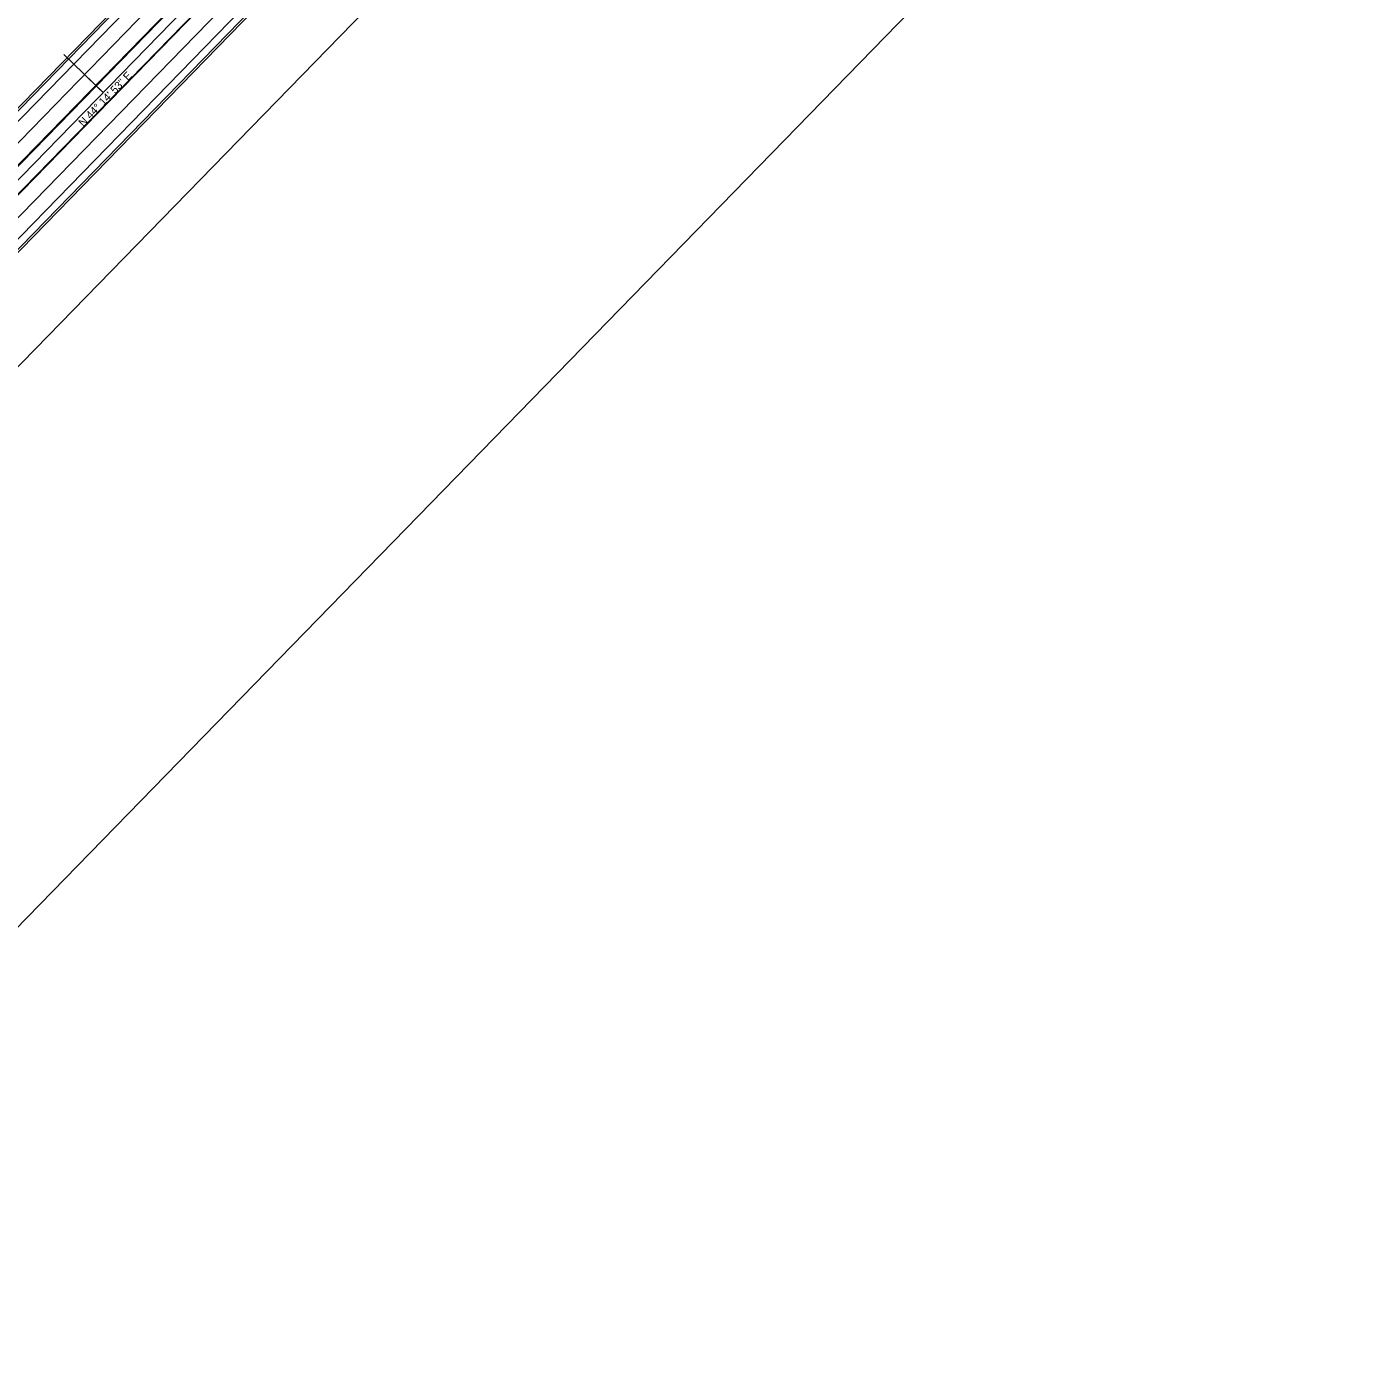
# Model space of a CAD drawing. Extents: x 2358865 to 2362945, y 393485 to 404880.
# Drawn here: x 2360577 to 2361590, y 398037 to 399070 of the extents above; entities that cross this region are included whole.
import ezdxf

# ---------------------------------------------------------------- set-up
doc = ezdxf.new("R2010")
doc.units = 0
for name, color, linetype in [('CL', 7, 'Continuous'), ('Level 19', 7, 'Continuous'), ('Level 21', 7, 'Continuous'), ('Level 25', 7, 'Continuous'), ('Level 27', 7, 'Continuous'), ('Level 30', 7, 'Continuous'), ('Level 35', 7, 'Continuous'), ('Level 37', 7, 'Continuous'), ('Level 39', 7, 'Continuous'), ('Level 41', 7, 'Continuous'), ('Level 48', 7, 'Continuous'), ('Level 58', 7, 'Continuous'), ('Level 63', 7, 'Continuous'), ('STAEQU', 7, 'Continuous')]:
    doc.layers.add(name, color=color, linetype=linetype)

msp = doc.modelspace()

# ---------------------------------------------------------------- linework, layer by layer
at = {"layer": 'CL'}
msp.add_line((2359688.9, 398047.8), (2361589.9, 399999.4), dxfattribs=at)
at = {"layer": 'Level 19'}
for p, q in [((2359821.6, 398212.7), (2361205.3, 399633.2)), ((2359850.3, 398184.8), (2361234, 399605.3))]:
    msp.add_line(p, q, dxfattribs=at)
at = {"layer": 'Level 25'}
msp.add_line((2360635.5, 399019.6), (2360631.9, 399023.1), dxfattribs=at)
at = {"layer": 'Level 27'}
msp.add_line((2359817.5, 398036.5), (2361439.8, 399702), dxfattribs=at)
at = {"layer": 'Level 30'}
msp.add_line((2360635.5, 399019.6), (2360629.4, 399025.5), dxfattribs=at)
at = {"layer": 'Level 35'}
for p, q in [((2359821.6, 398212.7), (2361205.3, 399633.2)), ((2359850.3, 398184.8), (2361234, 399605.3))]:
    msp.add_line(p, q, dxfattribs=at)
at = {"layer": 'Level 37'}
for p, q in [((2359830.2, 398204.4), (2361213.9, 399624.9)), ((2359830.6, 398204), (2361214.3, 399624.5)), ((2359841.3, 398193.6), (2361225, 399614)), ((2359841.7, 398193.2), (2361225.4, 399613.7))]:
    msp.add_line(p, q, dxfattribs=at)
at = {"layer": 'Level 39'}
msp.add_line((2360635.5, 399019.6), (2360623.3, 399031.5), dxfattribs=at)
at = {"layer": 'Level 41'}
msp.add_line((2360635.5, 399019.6), (2360605.4, 399048.9), dxfattribs=at)
at = {"layer": 'Level 48'}
for p, q in [((2361214.3, 399624.5), (2359830.6, 398204)), ((2359841.3, 398193.6), (2361225, 399614))]:
    msp.add_line(p, q, dxfattribs=at)
at = {"layer": 'Level 58'}
for p, q in [((2359947.9, 398369), (2361129.8, 399582.4)), ((2360003.2, 398315.1), (2361185.1, 399528.5))]:
    msp.add_line(p, q, dxfattribs=at)
at = {"layer": 'Level 63'}
msp.add_lwpolyline([(2360837.4, 399800.1), (2359790.8, 398725.6), (2360363.8, 398167.4), (2360363.8, 398167.4), (2361410.5, 399241.9), (2361410.5, 399241.9)], close=True, dxfattribs=at)
at = {"layer": 'STAEQU'}
for p, q in [((2359949, 398367.9), (2361193.1, 399645.1)), ((2361197.1, 399641.3), (2359953, 398364)), ((2359998.1, 398320.1), (2361242.2, 399597.3)), ((2361246.1, 399593.5), (2360002, 398316.2))]:
    msp.add_line(p, q, dxfattribs=at)

# ---------------------------------------------------------------- texts
at = {"layer": 'Level 21'}
msp.add_text('N 44%%d 14\' 53" E', height=6, rotation=45.7519, dxfattribs=at).set_placement((2360620.2, 398993.2))

doc.saveas('drawing.dxf')
